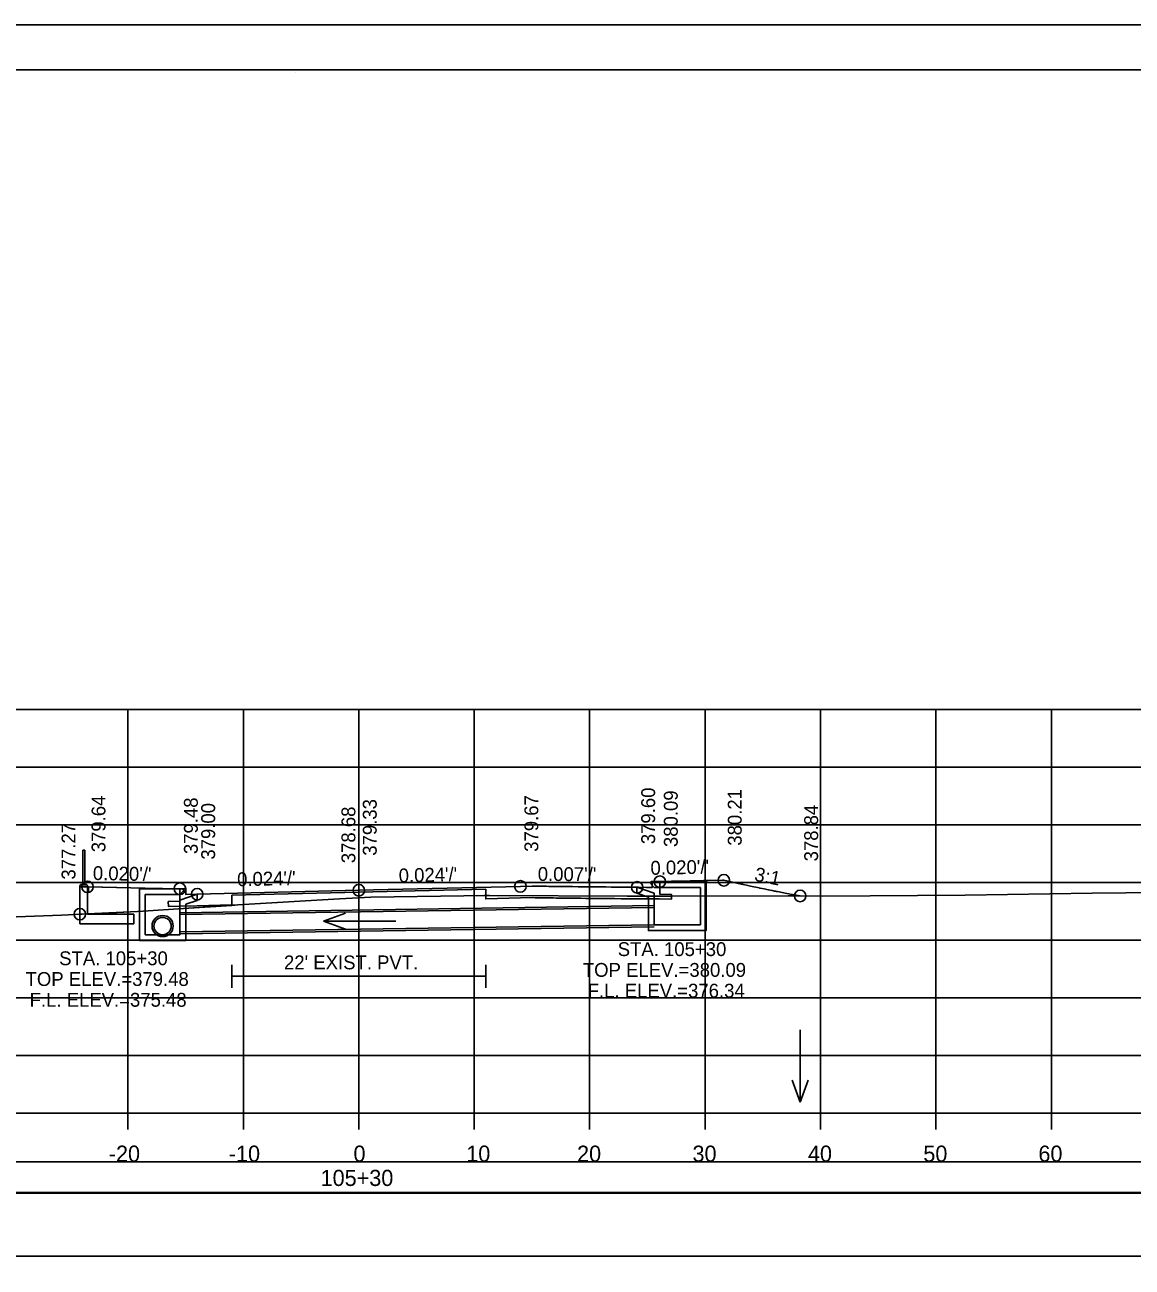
# Model space of a CAD drawing. Extents: x -37291014 to -37290680, y -936053 to -933067.
# Drawn here: x -37290872 to -37290776.1, y -934881 to -934773.3 of the extents above; entities that cross this region are included whole.
import ezdxf

# ---------------------------------------------------------------- set-up
doc = ezdxf.new("R2010")
doc.units = 0
for name, color, linetype in [('Default', 7, 'Continuous'), ('R_Alt Surface', 7, 'Continuous'), ('R_Axis', 7, 'Continuous'), ('R_Axis Annot', 7, 'Continuous'), ('R_Border', 7, 'Continuous'), ('R_Contours', 7, 'Continuous'), ('R_Exist Surface', 7, 'Continuous'), ('R_Fin Surface', 7, 'Continuous'), ('R_Grid', 7, 'Continuous'), ('R_No Plot', 7, 'Continuous'), ('R_Water', 7, 'Continuous'), ('R_Water Annot', 7, 'Continuous'), ('R_Xsect Elev', 7, 'Continuous'), ('R_Xsect Slope', 7, 'Continuous')]:
    doc.layers.add(name, color=color, linetype=linetype)

msp = doc.modelspace()

# ---------------------------------------------------------------- linework, layer by layer
at = {"layer": 'Default'}
for p, q in [((-37290867.02, -934847.81), (-37290867.02, -934844.81)), ((-37290867.02, -934844.81), (-37290866.85, -934844.81)), ((-37290866.85, -934844.81), (-37290866.85, -934847.81)), ((-37290867.21, -934847.83), (-37290867.27, -934847.89)), ((-37290867.27, -934847.89), (-37290867.27, -934851.2)), ((-37290866.66, -934847.81), (-37290867.21, -934847.81)), ((-37290867.21, -934847.81), (-37290867.21, -934847.83)), ((-37290866.66, -934847.83), (-37290867.21, -934847.83)), ((-37290866.66, -934847.83), (-37290866.66, -934847.81)), ((-37290866.6, -934847.89), (-37290866.66, -934847.83)), ((-37290866.6, -934850.37), (-37290866.6, -934847.89)), ((-37290862.6, -934850.37), (-37290866.6, -934850.37)), ((-37290862.6, -934851.2), (-37290862.6, -934850.37)), ((-37290862.6, -934851.2), (-37290867.27, -934851.2))]:
    msp.add_line(p, q, dxfattribs=at)
msp.add_lwpolyline([(-37290866.52, -934848.5), (-37290866.6, -934848.5), (-37290866.6, -934848), (-37290866.52, -934848), (-37290866.52, -934848.5)], dxfattribs=at)
for points in [[(-37290992.31, -934874.54), (-37290693.89, -934874.54), (-37290693.89, -934871.83), (-37290992.31, -934871.83)], [(-37290992.27, -934880.02), (-37290693.85, -934880.02), (-37290693.85, -934874.5), (-37290992.27, -934874.5)]]:
    msp.add_lwpolyline(points, close=True, dxfattribs=at)
at = {"layer": 'R_Alt Surface'}
for points in [[(-37290817.02, -934847.55), (-37290817.02, -934848.64), (-37290816.01, -934848.66), (-37290816.02, -934849.08), (-37290817.08, -934849.05)], [(-37290829.1, -934848.96), (-37290832.1, -934849.04), (-37290832.1, -934848.21), (-37290843.1, -934848.47), (-37290854.1, -934848.73), (-37290854.1, -934849.56), (-37290857.1, -934849.64), (-37290858.6, -934849.67), (-37290859.6, -934849.69), (-37290859.61, -934849.27), (-37290858.6, -934849.25), (-37290858.6, -934848.16)], [(-37290829.1, -934848.96), (-37290828.07, -934848.93), (-37290827.82, -934848.94), (-37290827.6, -934848.94), (-37290827.6, -934848.94), (-37290827.41, -934848.94), (-37290827.32, -934848.95), (-37290827.29, -934848.95), (-37290827.01, -934848.95), (-37290826.95, -934848.95), (-37290826.84, -934848.95), (-37290826.65, -934848.96), (-37290826.45, -934848.96), (-37290826.24, -934848.96), (-37290825.99, -934848.97), (-37290825.88, -934848.97), (-37290825.79, -934848.97), (-37290825.28, -934848.98), (-37290825.27, -934848.98), (-37290825.06, -934848.98), (-37290825.03, -934848.98), (-37290824.72, -934848.98), (-37290824.59, -934848.98), (-37290824.1, -934848.99), (-37290824.03, -934848.99), (-37290823.85, -934848.99), (-37290823.42, -934849), (-37290823.04, -934849), (-37290822.91, -934849), (-37290822.67, -934849), (-37290822.55, -934849.01), (-37290822.17, -934849.01), (-37290821.85, -934849.01), (-37290821.69, -934849.01), (-37290821.23, -934849.02), (-37290820.96, -934849.02), (-37290820.36, -934849.03), (-37290820.21, -934849.03), (-37290820, -934849.03), (-37290817.08, -934849.05)], [(-37290854.1, -934854.75), (-37290854.1, -934856.75)], [(-37290832.1, -934854.75), (-37290832.1, -934856.75)], [(-37290854.1, -934855.75), (-37290832.1, -934855.75)]]:
    msp.add_lwpolyline(points, dxfattribs=at)
at = {"layer": 'R_Axis'}
for p, q in [((-37290993.1, -934867.63), (-37290693.1, -934867.63)), ((-37290863.1, -934869.03), (-37290863.1, -934867.63)), ((-37290853.1, -934869.03), (-37290853.1, -934867.63)), ((-37290843.1, -934869.03), (-37290843.1, -934867.63)), ((-37290833.1, -934869.03), (-37290833.1, -934867.63)), ((-37290823.1, -934869.03), (-37290823.1, -934867.63)), ((-37290813.1, -934869.03), (-37290813.1, -934867.63)), ((-37290803.1, -934869.03), (-37290803.1, -934867.63)), ((-37290793.1, -934869.03), (-37290793.1, -934867.63)), ((-37290783.1, -934869.03), (-37290783.1, -934867.63))]:
    msp.add_line(p, q, dxfattribs=at)
at = {"layer": 'R_Border'}
for p, q in [((-37291001.1, -934777.17), (-37290684.92, -934777.17)), ((-37290848.58, -934777.43), (-37290848.58, -934777.43)), ((-37290848.58, -934777.43), (-37290848.58, -934777.43))]:
    msp.add_line(p, q, dxfattribs=at)
at = {"layer": 'R_Contours'}
for p, q in [((-37290866.6, -934848.5), (-37290866.6, -934850.33)), ((-37290832.1, -934848.76), (-37290832.1, -934849.04)), ((-37290804.87, -934848.79), (-37290805.39, -934848.69)), ((-37290854.1, -934849.56), (-37290854.1, -934849.61)), ((-37290854.1, -934849.56), (-37290854.1, -934849.61)), ((-37290854.1, -934849.61), (-37290854.1, -934849.56)), ((-37290832.1, -934849.04), (-37290829.1, -934848.96)), ((-37290866.6, -934850.33), (-37290867.27, -934850.37)), ((-37290866.6, -934850.37), (-37290866.6, -934850.33)), ((-37290862.6, -934850.37), (-37290866.6, -934850.37)), ((-37290862.6, -934851.2), (-37290862.6, -934850.37)), ((-37290867.27, -934851.2), (-37290862.6, -934851.2))]:
    msp.add_line(p, q, dxfattribs=at)
for points in [[(-37290805.39, -934848.69), (-37290805.41, -934848.69), (-37290805.54, -934848.66), (-37290805.58, -934848.66), (-37290805.84, -934848.61), (-37290806.02, -934848.57), (-37290806.83, -934848.41), (-37290806.87, -934848.4), (-37290806.92, -934848.39), (-37290807, -934848.38), (-37290807.1, -934848.36), (-37290807.3, -934848.32), (-37290807.62, -934848.25), (-37290807.97, -934848.18), (-37290808.33, -934848.11), (-37290808.38, -934848.1), (-37290808.42, -934848.09), (-37290809.16, -934847.93), (-37290809.52, -934847.85), (-37290809.8, -934847.79), (-37290809.89, -934847.78), (-37290809.95, -934847.76), (-37290809.97, -934847.76), (-37290811.48, -934847.43), (-37290811.52, -934847.43), (-37290811.57, -934847.43), (-37290811.6, -934847.43), (-37290812.82, -934847.46), (-37290813.23, -934847.46), (-37290813.27, -934847.47), (-37290813.34, -934847.47), (-37290813.61, -934847.47), (-37290813.78, -934847.48), (-37290814.39, -934847.49), (-37290814.93, -934847.5), (-37290814.99, -934847.5), (-37290815.03, -934847.5), (-37290815.08, -934847.5), (-37290815.18, -934847.51), (-37290816.02, -934847.52), (-37290816.2, -934847.53), (-37290816.91, -934847.54), (-37290816.92, -934847.54), (-37290817.02, -934847.55)], [(-37290817.02, -934847.55), (-37290817.02, -934848.64), (-37290816.01, -934848.66), (-37290816.01, -934848.81)], [(-37290866.52, -934848), (-37290866.52, -934848.5), (-37290866.6, -934848.5)], [(-37290858.6, -934848.16), (-37290861.6, -934848.1), (-37290866.52, -934848)], [(-37290854.1, -934849.56), (-37290857.1, -934849.64), (-37290858.6, -934849.67), (-37290859.6, -934849.69), (-37290859.61, -934849.27), (-37290858.6, -934849.25), (-37290858.6, -934848.16)], [(-37290832.1, -934848.76), (-37290832.1, -934848.21), (-37290843.1, -934848.47), (-37290854.1, -934848.73), (-37290854.1, -934849.56)], [(-37290854.1, -934849.61), (-37290853.58, -934849.57), (-37290844.77, -934849.04), (-37290842.06, -934848.89), (-37290833.99, -934848.78), (-37290832.26, -934848.76), (-37290832.1, -934848.76)], [(-37290816.01, -934848.81), (-37290817.1, -934848.81), (-37290819.85, -934848.81), (-37290831.79, -934848.76), (-37290832.1, -934848.76)], [(-37290817.08, -934849.05), (-37290816.02, -934849.08), (-37290816.01, -934848.81)], [(-37290816.01, -934848.81), (-37290805.91, -934848.79), (-37290804.87, -934848.79)], [(-37290866.6, -934850.33), (-37290862.28, -934850.14), (-37290861.79, -934850.12), (-37290858.3, -934849.87), (-37290854.1, -934849.61)], [(-37290829.1, -934848.96), (-37290828.07, -934848.93), (-37290827.82, -934848.94), (-37290827.6, -934848.94), (-37290827.41, -934848.94), (-37290827.32, -934848.95), (-37290827.29, -934848.95), (-37290827.01, -934848.95), (-37290826.95, -934848.95), (-37290826.84, -934848.95), (-37290826.65, -934848.96), (-37290826.45, -934848.96), (-37290826.24, -934848.96), (-37290825.99, -934848.97), (-37290825.88, -934848.97), (-37290825.79, -934848.97), (-37290825.28, -934848.98), (-37290825.27, -934848.98), (-37290825.06, -934848.98), (-37290825.03, -934848.98), (-37290824.72, -934848.98), (-37290824.59, -934848.98), (-37290824.1, -934848.99), (-37290824.03, -934848.99), (-37290823.85, -934848.99), (-37290823.42, -934849), (-37290823.04, -934849), (-37290822.91, -934849), (-37290822.67, -934849), (-37290822.55, -934849.01), (-37290822.17, -934849.01), (-37290821.85, -934849.01), (-37290821.69, -934849.01), (-37290821.23, -934849.02), (-37290820.96, -934849.02), (-37290820.36, -934849.03), (-37290820.21, -934849.03), (-37290820, -934849.03), (-37290817.08, -934849.05)], [(-37290867.27, -934850.37), (-37290867.27, -934850.37), (-37290867.27, -934851.2)]]:
    msp.add_lwpolyline(points, dxfattribs=at)
at = {"layer": 'R_Exist Surface'}
msp.add_lwpolyline([(-37290879.83, -934850.86), (-37290868.86, -934850.44), (-37290862.28, -934850.14), (-37290861.79, -934850.12), (-37290858.3, -934849.87), (-37290853.58, -934849.57), (-37290844.77, -934849.04), (-37290842.06, -934848.89), (-37290833.99, -934848.78), (-37290832.26, -934848.76), (-37290831.79, -934848.76), (-37290819.85, -934848.81), (-37290817.1, -934848.81), (-37290805.91, -934848.79), (-37290802.92, -934848.8), (-37290790.56, -934848.71), (-37290779.56, -934848.55), (-37290770.8, -934848.46)], dxfattribs=at)
at = {"layer": 'R_Fin Surface'}
for points in [[(-37290829.1, -934847.96), (-37290828.07, -934847.93), (-37290827.82, -934847.94), (-37290827.6, -934847.94), (-37290827.6, -934847.94), (-37290827.41, -934847.94), (-37290827.32, -934847.95), (-37290827.3, -934847.95), (-37290827.01, -934847.95), (-37290826.96, -934847.95), (-37290826.84, -934847.95), (-37290826.65, -934847.96), (-37290826.45, -934847.96), (-37290826.24, -934847.96), (-37290825.99, -934847.97), (-37290825.88, -934847.97), (-37290825.79, -934847.97), (-37290825.28, -934847.98), (-37290825.27, -934847.98), (-37290825.06, -934847.98), (-37290825.03, -934847.98), (-37290824.72, -934847.98), (-37290824.59, -934847.98), (-37290824.1, -934847.99), (-37290824.03, -934847.99), (-37290823.85, -934847.99), (-37290823.42, -934848), (-37290823.04, -934848), (-37290822.91, -934848), (-37290822.67, -934848), (-37290822.55, -934848.01), (-37290822.17, -934848.01), (-37290821.85, -934848.01), (-37290821.69, -934848.01), (-37290821.23, -934848.02), (-37290820.96, -934848.02), (-37290820.36, -934848.03), (-37290820.21, -934848.03), (-37290820, -934848.03), (-37290819.12, -934848.04), (-37290818.98, -934848.04), (-37290818.92, -934848.04), (-37290818.92, -934848.04), (-37290818.87, -934848.04), (-37290818.18, -934848.05), (-37290817.67, -934848.05), (-37290817.67, -934847.71), (-37290817.67, -934847.55), (-37290817.52, -934847.55), (-37290817.14, -934847.55), (-37290817.11, -934847.55), (-37290817.02, -934847.55), (-37290816.92, -934847.54), (-37290816.92, -934847.54), (-37290816.91, -934847.54), (-37290816.2, -934847.53), (-37290816.02, -934847.52), (-37290815.18, -934847.51), (-37290815.08, -934847.5), (-37290815.03, -934847.5), (-37290814.99, -934847.5), (-37290814.93, -934847.5), (-37290814.39, -934847.49), (-37290813.78, -934847.48), (-37290813.61, -934847.47), (-37290813.34, -934847.47), (-37290813.27, -934847.47), (-37290813.23, -934847.46), (-37290812.82, -934847.46), (-37290811.6, -934847.43), (-37290811.57, -934847.43), (-37290811.57, -934847.43), (-37290811.57, -934847.43), (-37290811.52, -934847.43), (-37290811.48, -934847.43), (-37290809.97, -934847.76), (-37290809.95, -934847.76), (-37290809.89, -934847.78), (-37290809.8, -934847.79), (-37290809.52, -934847.85), (-37290809.16, -934847.93), (-37290808.42, -934848.09), (-37290808.38, -934848.1), (-37290808.33, -934848.11), (-37290807.97, -934848.18), (-37290807.62, -934848.25), (-37290807.3, -934848.32), (-37290807.1, -934848.36), (-37290807, -934848.38), (-37290806.92, -934848.39), (-37290806.87, -934848.4), (-37290806.83, -934848.41), (-37290806.02, -934848.57), (-37290805.84, -934848.61), (-37290805.58, -934848.66), (-37290805.54, -934848.66), (-37290805.41, -934848.69), (-37290805.39, -934848.69), (-37290804.86, -934848.79)], [(-37290867.27, -934850.37), (-37290867.27, -934848), (-37290866.6, -934848), (-37290861.6, -934848.1), (-37290858.6, -934848.16), (-37290858.1, -934848.16), (-37290858.1, -934848.66), (-37290857.1, -934848.64), (-37290843.1, -934848.3), (-37290829.1, -934847.96)]]:
    msp.add_lwpolyline(points, dxfattribs=at)
at = {"layer": 'R_Grid'}
for p, q in [((-37290993.1, -934832.63), (-37290693.1, -934832.63)), ((-37290863.1, -934867.63), (-37290863.1, -934832.63)), ((-37290853.1, -934867.63), (-37290853.1, -934832.63)), ((-37290843.1, -934867.63), (-37290843.1, -934832.63)), ((-37290833.1, -934867.63), (-37290833.1, -934832.63)), ((-37290823.1, -934867.63), (-37290823.1, -934832.63)), ((-37290813.1, -934867.63), (-37290813.1, -934832.63)), ((-37290803.1, -934867.63), (-37290803.1, -934832.63)), ((-37290793.1, -934867.63), (-37290793.1, -934832.63)), ((-37290783.1, -934867.63), (-37290783.1, -934832.63)), ((-37290993.1, -934837.63), (-37290693.1, -934837.63)), ((-37290993.1, -934842.63), (-37290693.1, -934842.63)), ((-37290993.1, -934847.63), (-37290693.1, -934847.63)), ((-37290993.1, -934852.63), (-37290693.1, -934852.63)), ((-37290993.1, -934857.63), (-37290693.1, -934857.63)), ((-37290993.1, -934862.63), (-37290693.1, -934862.63)), ((-37290993.1, -934867.63), (-37290693.1, -934867.63))]:
    msp.add_line(p, q, dxfattribs=at)
at = {"layer": 'R_No Plot'}
for p, q in [((-37291013.5, -934773.28), (-37290680.17, -934773.28)), ((-37290817.51, -934849.63), (-37290858.6, -934850.24)), ((-37290817.51, -934851.46), (-37290858.6, -934852.07))]:
    msp.add_line(p, q, dxfattribs=at)
for points in [[(-37291013.51, -934773.28), (-37290680.17, -934773.28), (-37290680.17, -934986.62), (-37291013.51, -934986.62)], [(-37290767.18, -934777.17), (-37290747.56, -934777.17), (-37290747.56, -934787.05), (-37290731.45, -934787.05), (-37290708.25, -934787.05), (-37290708.25, -934811.39), (-37290684.92, -934811.39), (-37290684.92, -934982.63), (-37291001.1, -934982.63), (-37291001.1, -934777.17)]]:
    msp.add_lwpolyline(points, close=True, dxfattribs=at)
for centre, radius in [((-37290866.6, -934848), 0.5), ((-37290858.6, -934848.16), 0.5), ((-37290829.1, -934847.96), 0.5), ((-37290829.1, -934847.96), 0.5), ((-37290818.98, -934848.04), 0.5), ((-37290817.02, -934847.55), 0.5), ((-37290811.48, -934847.43), 0.5), ((-37290857.1, -934848.64), 0.5), ((-37290843.1, -934848.3), 0.5), ((-37290804.86, -934848.79), 0.5), ((-37290867.27, -934850.37), 0.5), ((-37290860.1, -934851.4), 0.917)]:
    msp.add_circle(centre, radius, dxfattribs=at)
at = {"layer": 'R_Water'}
for p, q in [((-37290817.84, -934847.71), (-37290817.76, -934847.55)), ((-37290817.84, -934847.71), (-37290817.51, -934848.05)), ((-37290813.01, -934847.55), (-37290817.76, -934847.55)), ((-37290813.01, -934849.05), (-37290813.01, -934847.55)), ((-37290862.1, -934848.16), (-37290858.35, -934848.16)), ((-37290861.6, -934848.66), (-37290858.6, -934848.66)), ((-37290858.27, -934848.32), (-37290858.6, -934848.66)), ((-37290857.1, -934848.64), (-37290858.6, -934849.16)), ((-37290858.27, -934848.32), (-37290858.35, -934848.16)), ((-37290819.01, -934848.03), (-37290817.51, -934848.55)), ((-37290819.01, -934848.56), (-37290818.01, -934848.9)), ((-37290813.51, -934848.05), (-37290817.51, -934848.05)), ((-37290817.51, -934849.05), (-37290817.51, -934848.55)), ((-37290813.51, -934849.05), (-37290813.51, -934848.05)), ((-37290858.6, -934849.66), (-37290858.6, -934849.16)), ((-37290817.51, -934849.79), (-37290858.6, -934850.4)), ((-37290857.1, -934849.17), (-37290858.1, -934849.51)), ((-37290858.1, -934849.66), (-37290858.1, -934849.51)), ((-37290818.01, -934849.05), (-37290818.01, -934848.9)), ((-37290817.51, -934851.29), (-37290858.6, -934851.9))]:
    msp.add_line(p, q, dxfattribs=at)
for points in [[(-37290858.1, -934849.66), (-37290858.1, -934852.65), (-37290860.1, -934852.65), (-37290862.1, -934852.65), (-37290862.1, -934848.16)], [(-37290858.6, -934849.66), (-37290858.6, -934852.15), (-37290860.1, -934852.15), (-37290861.6, -934852.15), (-37290861.6, -934848.66)], [(-37290857.1, -934849.17), (-37290857.1, -934848.64)], [(-37290819.01, -934848.56), (-37290819.01, -934848.03)], [(-37290813.01, -934849.05), (-37290813.01, -934851.79), (-37290815.51, -934851.79), (-37290818.01, -934851.79), (-37290818.01, -934849.05)], [(-37290813.51, -934849.05), (-37290813.51, -934851.29), (-37290815.51, -934851.29), (-37290817.51, -934851.29), (-37290817.51, -934849.05)]]:
    msp.add_lwpolyline(points, dxfattribs=at)
msp.add_circle((-37290860.1, -934851.4), 0.75, dxfattribs=at)
at = {"layer": 'R_Water Annot'}
for p, q in [((-37290846.17, -934850.97), (-37290844.25, -934850.27)), ((-37290839.89, -934850.97), (-37290846.17, -934850.97)), ((-37290846.17, -934850.97), (-37290844.25, -934851.67)), ((-37290804.86, -934860.39), (-37290804.86, -934866.67)), ((-37290804.86, -934866.67), (-37290805.56, -934864.75)), ((-37290804.86, -934866.67), (-37290804.16, -934864.75))]:
    msp.add_line(p, q, dxfattribs=at)
at = {"layer": 'R_Xsect Elev'}
msp.add_line((-37290843.1, -934848.95), (-37290843.1, -934838.95), dxfattribs=at)

# ---------------------------------------------------------------- texts
at = {"layer": 'R_Axis Annot'}
for s, p in [('-20', (-37290864.76, -934871.83)), ('-10', (-37290854.36, -934871.83)), ('0', (-37290843.56, -934871.83)), ('10', (-37290833.79, -934871.83)), ('20', (-37290824.19, -934871.83)), ('30', (-37290814.19, -934871.83)), ('40', (-37290804.19, -934871.83)), ('50', (-37290794.19, -934871.83)), ('60', (-37290784.22, -934871.83)), ('105+30', (-37290846.41, -934873.93))]:
    msp.add_text(s, height=1.4, dxfattribs=at).set_placement(p)
at = {"layer": 'R_Water'}
msp.add_text("22' EXIST. PVT.", height=1.2, dxfattribs=at).set_placement((-37290849.58, -934855.15))
at = {"layer": 'R_Water Annot'}
for s, p in [('STA. 105+30', (-37290820.67, -934854)), ('STA. 105+30', (-37290869.06, -934854.79)), ('TOP ELEV.=380.09', (-37290823.69, -934855.8)), ('TOP ELEV.=379.48', (-37290871.97, -934856.59)), ('F.L. ELEV.=375.48', (-37290871.62, -934858.39)), ('F.L. ELEV.=376.34', (-37290823.27, -934857.6))]:
    msp.add_text(s, height=1.2, dxfattribs=at).set_placement(p)
at = {"layer": 'R_Xsect Elev'}
for s, rotation, p in [('379.64', 90, (-37290865.05, -934845)), ('379.67', 90, (-37290827.55, -934844.96)), ('379.60', 90, (-37290817.43, -934844.3)), ('380.09', 90, (-37290815.47, -934844.55)), ('380.21', 90, (-37290809.93, -934844.43)), ('379.48', 90, (-37290857.05, -934845.16)), ('379.00', 90, (-37290855.55, -934845.64)), ('378.68', 90, (-37290843.4, -934845.95)), ('379.33', 90, (-37290841.55, -934845.3)), ('378.84', 90, (-37290803.31, -934845.79)), ('377.27', 90, (-37290867.65, -934847.37)), ("0.007'/'", 359.5786, (-37290827.6, -934847.48))]:
    msp.add_text(s, height=1.2, rotation=rotation, dxfattribs=at).set_placement(p)
at = {"layer": 'R_Xsect Slope'}
for s, rotation, p in [("0.020'/'", 1.2258, (-37290817.82, -934846.96)), ("0.020'/'", 358.8542, (-37290866.15, -934847.4)), ("0.024'/'", 1.3748, (-37290853.63, -934847.95)), ("0.024'/'", 1.3748, (-37290839.63, -934847.62)), ('3:1', 348.3632, (-37290808.89, -934847.45))]:
    msp.add_text(s, height=1.2, rotation=rotation, dxfattribs=at).set_placement(p)

doc.saveas('drawing.dxf')
